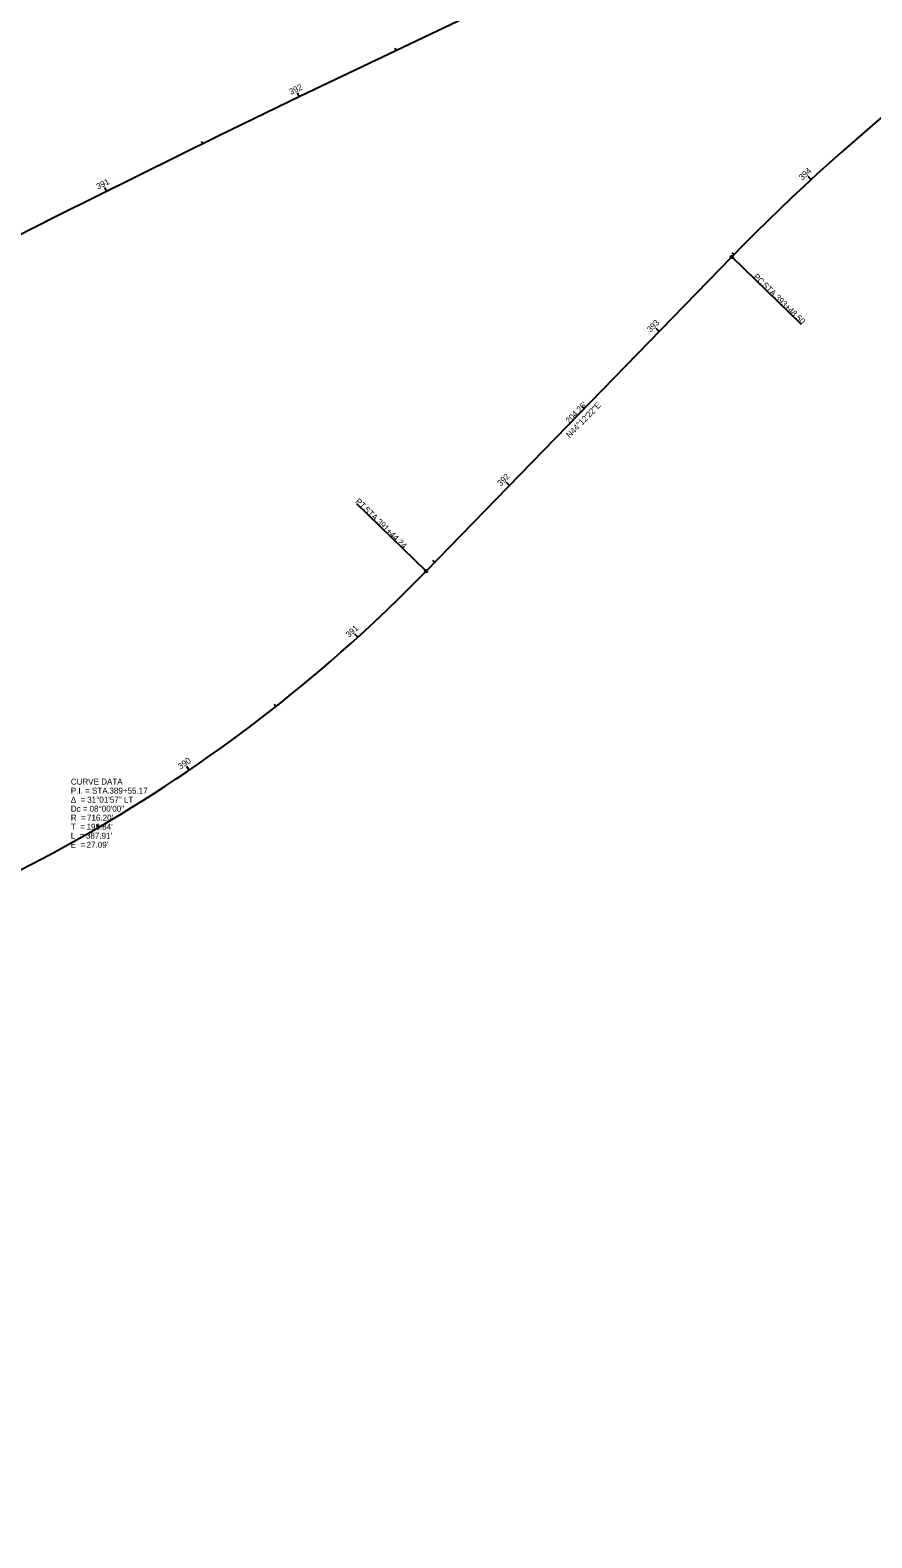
# Model space of a CAD drawing. Extents: x 2138583 to 2143699, y 639707 to 641182.
# Drawn here: x 2139588 to 2139980, y 639745 to 640448 of the extents above; entities that cross this region are included whole.
import ezdxf

# ---------------------------------------------------------------- set-up
doc = ezdxf.new("R2010")
doc.units = 0
for name, color, linetype in [('GE_X_Alignment', 7, 'Continuous'), ('GE_X_Alignment_100_Bearings', 7, 'Continuous'), ('GE_X_Alignment_100_Cardinal_Points', 7, 'Continuous'), ('GE_X_Alignment_100_Curve_Data', 7, 'Continuous'), ('GE_X_Alignment_100_Distances', 7, 'Continuous'), ('GE_X_Alignment_100_Stations', 7, 'Continuous'), ('RW_X_CL', 7, 'Continuous'), ('RW_X_CL_100_Stations', 7, 'Continuous')]:
    doc.layers.add(name, color=color, linetype=linetype)

msp = doc.modelspace()

# ---------------------------------------------------------------- linework, layer by layer
at = {"layer": 'GE_X_Alignment'}
msp.add_line((2139772.4, 640195.49), (2139914.82, 640341.91), dxfattribs=at)
for centre, radius, start, end in [((2140599.34, 639676.11), 954.92, 120.70421, 135.79393), ((2139259, 640694.86), 716.2, 284.76143, 315.79393)]:
    msp.add_arc(centre, radius, start, end, dxfattribs=at)
at = {"layer": 'GE_X_Alignment_100_Cardinal_Points'}
for p, q in [((2139914.82, 640341.91), (2139947.08, 640310.54)), ((2139772.4, 640195.49), (2139740.14, 640226.87))]:
    msp.add_line(p, q, dxfattribs=at)
for centre in [(2139914.82, 640341.91), (2139772.4, 640195.49)]:
    msp.add_circle(centre, 0.6, dxfattribs=at)
at = {"layer": 'GE_X_Alignment_100_Stations'}
for p, q in [((2139951.71, 640377.85), (2139950.35, 640379.32)), ((2139915.87, 640342.99), (2139915.01, 640343.83)), ((2139881, 640307.15), (2139879.57, 640308.54)), ((2139846.14, 640271.31), (2139845.28, 640272.14)), ((2139811.28, 640235.47), (2139809.85, 640236.86)), ((2139776.42, 640199.62), (2139775.56, 640200.46)), ((2139740.6, 640164.75), (2139739.25, 640166.23)), ((2139702.45, 640132.45), (2139701.7, 640133.39)), ((2139662.13, 640102.89), (2139661.01, 640104.54)), ((2139619.86, 640076.21), (2139619.25, 640077.25))]:
    msp.add_line(p, q, dxfattribs=at)
at = {"layer": 'RW_X_CL'}
msp.add_arc((2143034.99, 633536.97), 7639.44, 85.029584, 125.643473, dxfattribs=at)
at = {"layer": 'RW_X_CL_100_Stations'}
for p, q in [((2139758.52, 640438.11), (2139758.01, 640439.2)), ((2139713.42, 640416.52), (2139712.55, 640418.32)), ((2139668.47, 640394.63), (2139667.94, 640395.71)), ((2139623.66, 640372.45), (2139622.77, 640374.24))]:
    msp.add_line(p, q, dxfattribs=at)

# ---------------------------------------------------------------- texts
at = {"layer": 'GE_X_Alignment_100_Bearings'}
msp.add_text('N44°12\'22"E', height=2.8, rotation=45.79393, dxfattribs=at).set_placement((2139839.3, 640257.39))
at = {"layer": 'GE_X_Alignment_100_Cardinal_Points'}
for s, p in [('PC', (2139924.64, 640332.41)), (' STA. ', (2139927.94, 640329.21)), ('393+48.50', (2139934.62, 640322.71)), ('PT', (2139739.29, 640227.75)), (' STA. ', (2139742.41, 640224.72)), ('391+44.24', (2139749.09, 640218.22))]:
    msp.add_text(s, height=2.8, rotation=315.79393, dxfattribs=at).set_placement(p)
at = {"layer": 'GE_X_Alignment_100_Curve_Data'}
for s, p in [('CURVE DATA', (2139606.94, 640096.09)), ('P.I. = STA. ', (2139606.94, 640091.89)), ('389+55.17', (2139624.93, 640091.89)), ('Δ  = ', (2139606.94, 640087.69)), ('31°01\'57" LT', (2139614.59, 640087.69)), ('Dc = ', (2139606.94, 640083.49)), ('R  = ', (2139606.94, 640079.29)), ("716.20'", (2139614.48, 640079.29)), ('08°00\'00"', (2139615.69, 640083.49)), ('T  = ', (2139606.94, 640075.09)), ('L  = ', (2139606.94, 640070.89)), ("387.91'", (2139613.98, 640070.89)), ("198.84'", (2139614.26, 640075.09)), ('E  = ', (2139606.94, 640066.69)), ("27.09'", (2139614.29, 640066.69))]:
    msp.add_text(s, height=2.8, dxfattribs=at).set_placement(p)
at = {"layer": 'GE_X_Alignment_100_Distances'}
msp.add_text("204.26'", height=2.8, rotation=45.79393, dxfattribs=at).set_placement((2139839.09, 640264.12))
at = {"layer": 'GE_X_Alignment_100_Stations'}
for s, rotation, p in [('394', 42.70376, (2139947.6, 640377.46)), ('393', 45.79393, (2139876.98, 640306.6)), ('392', 45.79393, (2139807.25, 640234.91)), ('391', 42.25492, (2139736.53, 640164.44)), ('390', 34.25496, (2139658.03, 640103.12))]:
    msp.add_text(s, height=2.8, rotation=rotation, dxfattribs=at).set_placement(p)
at = {"layer": 'RW_X_CL_100_Stations'}
for s, rotation, p in [('392', 25.77205, (2139709.45, 640417.38)), ('391', 26.52205, (2139619.66, 640373.25))]:
    msp.add_text(s, height=2.8, rotation=rotation, dxfattribs=at).set_placement(p)

doc.saveas('drawing.dxf')
